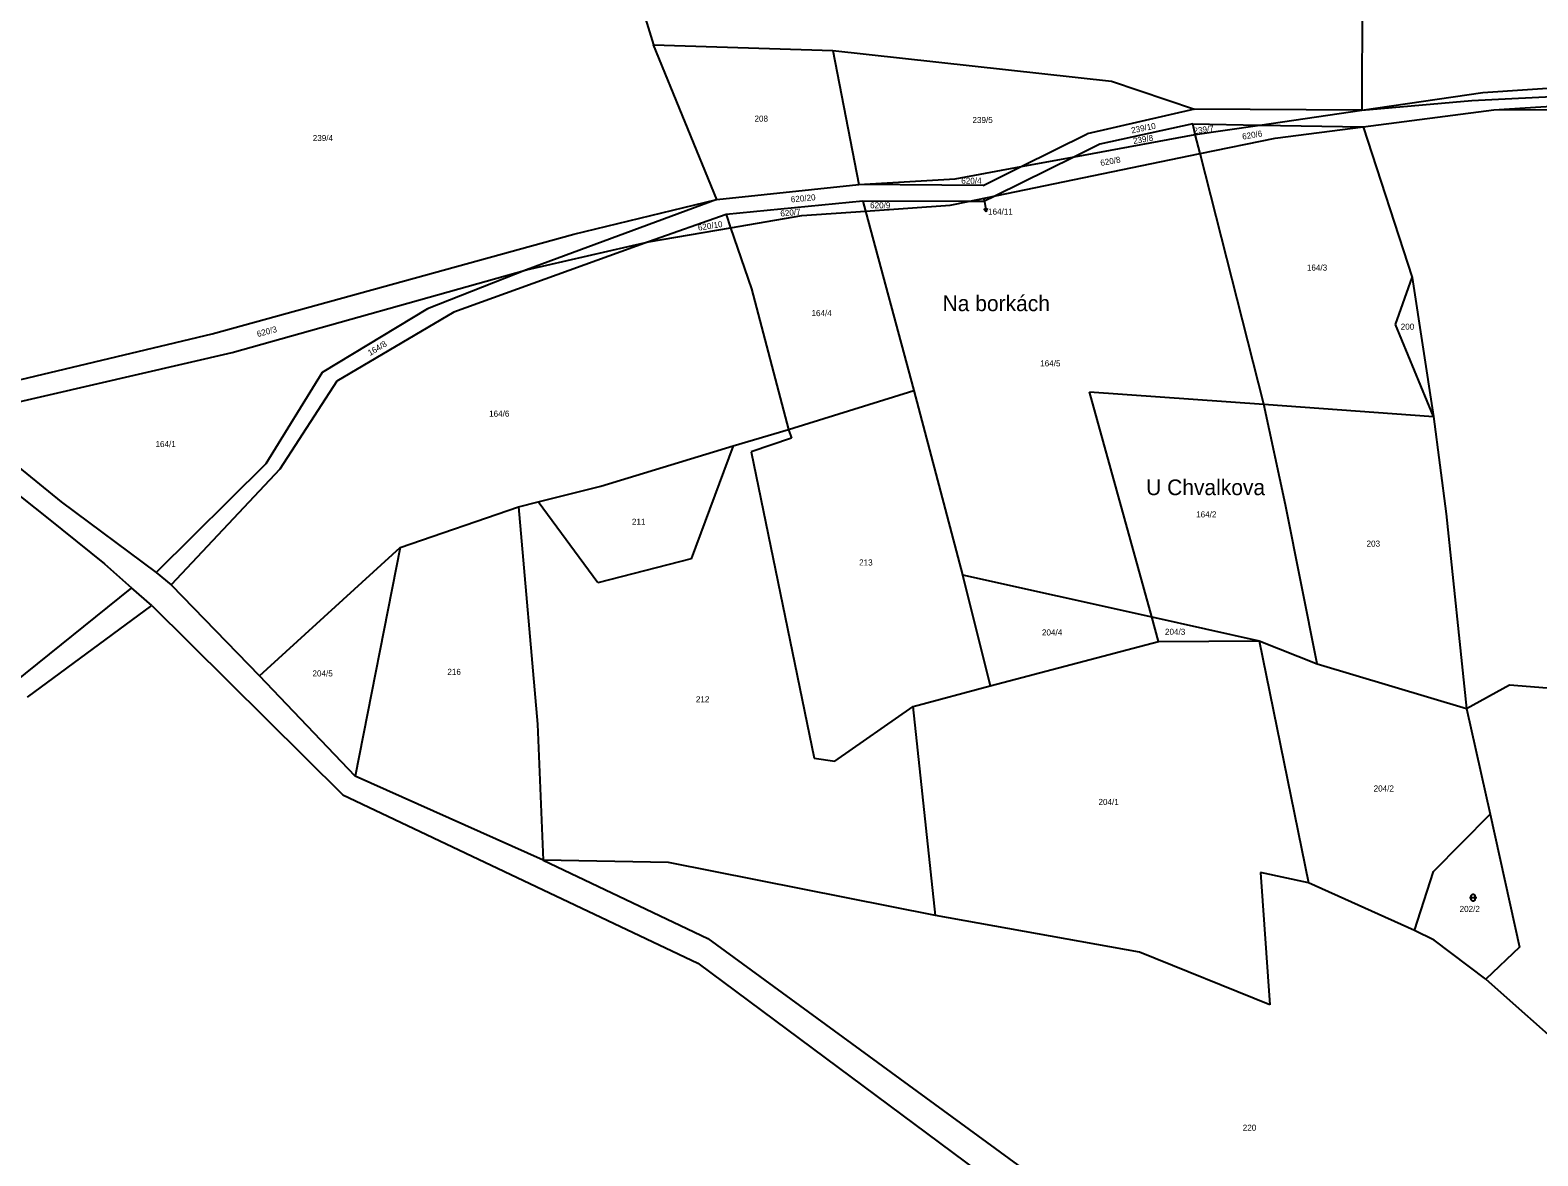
# Model space of a CAD drawing. Extents: x -794421 to -792735, y -1117671 to -1115559.
# Drawn here: x -794007.8 to -793585, y -1116417 to -1116101.2 of the extents above; entities that cross this region are included whole.
import ezdxf

# ---------------------------------------------------------------- set-up
doc = ezdxf.new("R2010")
doc.units = 0
for name, color, linetype in [('Komunikace', 7, 'Continuous'), ('Vrstva 1', 7, 'Continuous'), ('Vrstva 14', 7, 'Continuous'), ('Vrstva 16', 7, 'Continuous'), ('Vrstva 23', 7, 'Continuous'), ('Vrstva 39', 7, 'Continuous')]:
    doc.layers.add(name, color=color, linetype=linetype)

msp = doc.modelspace()

# ---------------------------------------------------------------- linework, layer by layer
at = {"layer": 'Komunikace'}
msp.add_line((-793740.29, -1116148.63), (-793740.17, -1116149.3), dxfattribs=at)
at = {"layer": 'Vrstva 1'}
for p, q in [((-793841.9, -1116076.14), (-793832.93, -1116105.39)), ((-793634.16, -1116081.65), (-793634.36, -1116123.68)), ((-793832.93, -1116105.39), (-793782.69, -1116106.95)), ((-793815.18, -1116148.79), (-793832.93, -1116105.39)), ((-793782.69, -1116106.95), (-793775.4, -1116144.58)), ((-793782.69, -1116106.95), (-793704.56, -1116115.56)), ((-793704.56, -1116115.56), (-793681.22, -1116123.41)), ((-793600.44, -1116118.71), (-793553.62, -1116115.56)), ((-793634.36, -1116123.68), (-793600.44, -1116118.71)), ((-793603.53, -1116120.99), (-793558.72, -1116118.73)), ((-793681.22, -1116123.41), (-793711.33, -1116130.35)), ((-793634.36, -1116123.68), (-793681.22, -1116123.41)), ((-793662.98, -1116127.87), (-793634.36, -1116123.68)), ((-793634.36, -1116123.68), (-793603.53, -1116120.99)), ((-793633.97, -1116128.34), (-793597.29, -1116123.63)), ((-793597.29, -1116123.63), (-793555.45, -1116120.83)), ((-793597.29, -1116123.63), (-793557.09, -1116123.33)), ((-793681.73, -1116127.56), (-793707.83, -1116133.26)), ((-793681.73, -1116127.56), (-793662.98, -1116127.87)), ((-793681.05, -1116130.51), (-793681.73, -1116127.56)), ((-793681.05, -1116130.51), (-793662.98, -1116127.87)), ((-793662.98, -1116127.87), (-793633.97, -1116128.34)), ((-793658.65, -1116131.51), (-793633.97, -1116128.34)), ((-793633.97, -1116128.34), (-793620.23, -1116170.63)), ((-793729.84, -1116139.53), (-793711.33, -1116130.35)), ((-793714.95, -1116136.78), (-793681.05, -1116130.51)), ((-793679.69, -1116135.86), (-793681.05, -1116130.51)), ((-793679.69, -1116135.86), (-793658.65, -1116131.51)), ((-793737.07, -1116147.71), (-793679.69, -1116135.86)), ((-793714.95, -1116136.78), (-793737.07, -1116147.71)), ((-793729.84, -1116139.53), (-793714.95, -1116136.78)), ((-793707.83, -1116133.26), (-793714.95, -1116136.78)), ((-793661.85, -1116206.2), (-793679.69, -1116135.86)), ((-793748.37, -1116142.95), (-793729.84, -1116139.53)), ((-793740.53, -1116144.84), (-793729.84, -1116139.53)), ((-793815.18, -1116148.79), (-793775.4, -1116144.58)), ((-793775.4, -1116144.58), (-793748.37, -1116142.95)), ((-793740.53, -1116144.84), (-793775.4, -1116144.58)), ((-793815.18, -1116148.79), (-793868.58, -1116168.47)), ((-793855.28, -1116158.46), (-793815.18, -1116148.79)), ((-793774.26, -1116149.18), (-793812.61, -1116152.91)), ((-793774.26, -1116149.18), (-793773.5, -1116152)), ((-793744.73, -1116149.29), (-793774.26, -1116149.18)), ((-793749.76, -1116150.33), (-793744.73, -1116149.29)), ((-793744.73, -1116149.29), (-793737.07, -1116147.71)), ((-793740.29, -1116149.3), (-793744.73, -1116149.29)), ((-793737.07, -1116147.71), (-793740.29, -1116149.3)), ((-793812.61, -1116152.91), (-793834.33, -1116160.6)), ((-793812.61, -1116152.91), (-793811.33, -1116156.67)), ((-793811.33, -1116156.67), (-793791.34, -1116153.26)), ((-793791.34, -1116153.26), (-793773.5, -1116152)), ((-793773.5, -1116152), (-793749.76, -1116150.33)), ((-793773.5, -1116152), (-793759.99, -1116202.28)), ((-793956.73, -1116186.47), (-793855.28, -1116158.46)), ((-793834.33, -1116160.6), (-793811.33, -1116156.67)), ((-793811.33, -1116156.67), (-793805.49, -1116173.76)), ((-793834.33, -1116160.6), (-793888.92, -1116180.33)), ((-793868.58, -1116168.47), (-793834.33, -1116160.6)), ((-793951.13, -1116191.65), (-793868.58, -1116168.47)), ((-793868.58, -1116168.47), (-793896.31, -1116179.37)), ((-793624.93, -1116183.83), (-793620.23, -1116170.63)), ((-793620.23, -1116170.63), (-793614.28, -1116209.62)), ((-793805.49, -1116173.76), (-793795.07, -1116213.26)), ((-793896.31, -1116179.37), (-793925.86, -1116197.25)), ((-793888.92, -1116180.33), (-793921.75, -1116199.71)), ((-793614.28, -1116209.62), (-793624.93, -1116183.83)), ((-794016.69, -1116200.78), (-793956.73, -1116186.47)), ((-794016.19, -1116206.71), (-793951.13, -1116191.65)), ((-793925.86, -1116197.25), (-793941.64, -1116222.86)), ((-793921.75, -1116199.71), (-793937.73, -1116224.43)), ((-793795.07, -1116213.26), (-793759.99, -1116202.28)), ((-793759.99, -1116202.28), (-793746.34, -1116254.05)), ((-793710.72, -1116202.69), (-793661.85, -1116206.2)), ((-793693.24, -1116265.77), (-793710.72, -1116202.69)), ((-793655.76, -1116234.44), (-793661.85, -1116206.2)), ((-793661.85, -1116206.2), (-793614.28, -1116209.62)), ((-794035.23, -1116212.34), (-794002.75, -1116238.27)), ((-793810.67, -1116217.86), (-793795.07, -1116213.26)), ((-793795.07, -1116213.26), (-793794.27, -1116215.71)), ((-793614.28, -1116209.62), (-793610.7, -1116236.94)), ((-794020.03, -1116216.53), (-793999.05, -1116233.58)), ((-793794.27, -1116215.71), (-793805.56, -1116219.56)), ((-793847.73, -1116229.19), (-793810.67, -1116217.86)), ((-793810.67, -1116217.86), (-793822.4, -1116249.55)), ((-793805.56, -1116219.56), (-793787.88, -1116305.47)), ((-793941.64, -1116222.86), (-793972.42, -1116253.42)), ((-793937.73, -1116224.43), (-793968.22, -1116256.81)), ((-793865.31, -1116233.55), (-793847.73, -1116229.19)), ((-793999.05, -1116233.58), (-793972.42, -1116253.42)), ((-793870.8, -1116234.91), (-793865.31, -1116233.55)), ((-793848.6, -1116256.32), (-793865.31, -1116233.55)), ((-793646.86, -1116278.95), (-793655.76, -1116234.44)), ((-794002.75, -1116238.27), (-793986.93, -1116250.95)), ((-793903.96, -1116246.38), (-793870.8, -1116234.91)), ((-793870.8, -1116234.91), (-793865.46, -1116295.94)), ((-793610.7, -1116236.94), (-793604.97, -1116291.48)), ((-793943.43, -1116282.4), (-793903.96, -1116246.38)), ((-793903.96, -1116246.38), (-793916.64, -1116310.52)), ((-793986.93, -1116250.95), (-793979.33, -1116257.63)), ((-793822.4, -1116249.55), (-793848.6, -1116256.32)), ((-793972.42, -1116253.42), (-793968.22, -1116256.81)), ((-793746.34, -1116254.05), (-793693.24, -1116265.77)), ((-793746.34, -1116254.05), (-793738.56, -1116285.15)), ((-793979.33, -1116257.63), (-794012.56, -1116284.39)), ((-793973.68, -1116262.66), (-793979.33, -1116257.63)), ((-793968.22, -1116256.81), (-793943.43, -1116282.4)), ((-794008.55, -1116288.34), (-793973.68, -1116262.66)), ((-793973.68, -1116262.66), (-793920.04, -1116315.71)), ((-793693.24, -1116265.77), (-793663.09, -1116272.5)), ((-793691.31, -1116272.74), (-793693.24, -1116265.77)), ((-793738.56, -1116285.15), (-793691.31, -1116272.74)), ((-793691.31, -1116272.74), (-793663.09, -1116272.5)), ((-793663.09, -1116272.5), (-793649.32, -1116340.43)), ((-793663.09, -1116272.5), (-793646.86, -1116278.95)), ((-793646.86, -1116278.95), (-793604.97, -1116291.48)), ((-793916.64, -1116310.52), (-793943.43, -1116282.4)), ((-793760.11, -1116290.96), (-793738.56, -1116285.15)), ((-793604.97, -1116291.48), (-793592.97, -1116284.93)), ((-793592.97, -1116284.93), (-793558.4, -1116287.58)), ((-793782.07, -1116306.26), (-793760.11, -1116290.96)), ((-793753.92, -1116349.61), (-793760.11, -1116290.96)), ((-793604.97, -1116291.48), (-793598.37, -1116321.17)), ((-793865.46, -1116295.94), (-793863.86, -1116334.03)), ((-793787.88, -1116305.47), (-793782.07, -1116306.26)), ((-793863.86, -1116334.03), (-793916.64, -1116310.52)), ((-793920.04, -1116315.71), (-793820.52, -1116362.92)), ((-793614.27, -1116337.29), (-793598.37, -1116321.17)), ((-793598.37, -1116321.17), (-793590.13, -1116358.46)), ((-793828.77, -1116334.72), (-793863.86, -1116334.03)), ((-793863.86, -1116334.03), (-793817.71, -1116356.03)), ((-793753.92, -1116349.61), (-793828.77, -1116334.72)), ((-793649.32, -1116340.43), (-793662.76, -1116337.54)), ((-793662.76, -1116337.54), (-793660.1, -1116374.64)), ((-793619.6, -1116353.8), (-793614.27, -1116337.29)), ((-793619.6, -1116353.8), (-793649.32, -1116340.43)), ((-793696.72, -1116359.85), (-793753.92, -1116349.61)), ((-793817.71, -1116356.03), (-793707.67, -1116436.43)), ((-793614.07, -1116356.51), (-793619.6, -1116353.8)), ((-793599.56, -1116367.45), (-793614.07, -1116356.51)), ((-793660.1, -1116374.64), (-793696.72, -1116359.85)), ((-793590.13, -1116358.46), (-793599.56, -1116367.45)), ((-793820.52, -1116362.92), (-793715.41, -1116441.11)), ((-793599.56, -1116367.45), (-793573.29, -1116390.8))]:
    msp.add_line(p, q, dxfattribs=at)
at = {"layer": 'Vrstva 16'}
for p, q in [((-793740.17, -1116149.3), (-793739.631, -1116152.251)), ((-793739.631, -1116152.251), (-793740.303, -1116151.357)), ((-793739.631, -1116152.251), (-793739.319, -1116151.177))]:
    msp.add_line(p, q, dxfattribs=at)
at = {"layer": 'Vrstva 23'}
for p, q in [((-793604.13, -1116344.56), (-793602.13, -1116344.56)), ((-793603.63, -1116343.96), (-793603.53, -1116343.76)), ((-793603.63, -1116345.16), (-793603.63, -1116343.96)), ((-793603.53, -1116343.76), (-793603.43, -1116343.66)), ((-793603.43, -1116343.66), (-793603.23, -1116343.56)), ((-793603.23, -1116343.56), (-793603.03, -1116343.56)), ((-793603.03, -1116343.56), (-793602.83, -1116343.66)), ((-793602.83, -1116343.66), (-793602.73, -1116343.76)), ((-793602.73, -1116343.76), (-793602.63, -1116343.96)), ((-793602.63, -1116343.96), (-793602.63, -1116345.16)), ((-793603.53, -1116345.36), (-793603.63, -1116345.16)), ((-793603.43, -1116345.46), (-793603.53, -1116345.36)), ((-793603.23, -1116345.56), (-793603.43, -1116345.46)), ((-793603.03, -1116345.56), (-793603.23, -1116345.56)), ((-793602.83, -1116345.46), (-793603.03, -1116345.56)), ((-793602.73, -1116345.36), (-793602.83, -1116345.46)), ((-793602.63, -1116345.16), (-793602.73, -1116345.36))]:
    msp.add_line(p, q, dxfattribs=at)

# ---------------------------------------------------------------- texts
at = {"layer": 'Vrstva 14'}
for s, height, p in [('208', 1.7, (-793804.646, -1116126.91)), ('239/5', 1.7, (-793743.526, -1116127.3)), ('239/4', 1.7, (-793928.516, -1116132.35)), ('620/4', 1.7, (-793746.665, -1116144.35)), ('620/9', 1.7, (-793772.229, -1116151.22)), ('164/11', 0.1, (-793740.497, -1116148.63)), ('164/3', 1.7, (-793649.739, -1116168.7)), ('164/4', 1.7, (-793788.665, -1116181.47)), ('200', 1.7, (-793623.425, -1116185.26)), ('164/5', 1.7, (-793724.525, -1116195.55)), ('164/6', 1.7, (-793879.059, -1116209.66)), ('164/1', 1.7, (-793972.622, -1116218.2)), ('211', 1.7, (-793839.013, -1116239.98)), ('164/2', 1.7, (-793680.799, -1116237.93)), ('203', 1.7, (-793633.006, -1116246.12)), ('213', 1.7, (-793775.3, -1116251.41)), ('204/4', 1.7, (-793724.041, -1116271.04)), ('204/3', 1.7, (-793689.535, -1116270.86)), ('204/5', 1.7, (-793928.591, -1116282.53)), ('216', 1.7, (-793890.77, -1116282.09)), ('212', 1.7, (-793821.08, -1116289.78)), ('204/2', 1.7, (-793631.025, -1116314.81)), ('204/1', 1.7, (-793708.178, -1116318.58)), ('202/2', 1.7, (-793606.919, -1116348.59)), ('220', 1.7, (-793667.726, -1116409.95))]:
    msp.add_text(s, height=height, dxfattribs=at).set_placement(p)
for s, rotation, p in [('239/10', 11.20077, (-793698.816, -1116130.219)), ('239/7', 7.12296, (-793681.419, -1116130.349)), ('239/8', 9.73251, (-793698.329, -1116133.19)), ('620/6', 9.65097, (-793667.74, -1116131.966)), ('620/8', 9.89307, (-793707.497, -1116139.337)), ('620/20', 5.2299, (-793794.38, -1116149.585)), ('620/7', 5.5377, (-793797.309, -1116153.551)), ('620/10', 9.07677, (-793820.371, -1116157.521)), ('620/3', 14.88375, (-793943.932, -1116187.338)), ('164/8', 30.88107, (-793912.44, -1116192.652))]:
    msp.add_text(s, height=1.7, rotation=rotation, dxfattribs=at).set_placement(p)
at = {"layer": 'Vrstva 16'}
msp.add_text('164/11', height=1.7, dxfattribs=at).set_placement((-793739.15, -1116152.99))
at = {"layer": 'Vrstva 39'}
for s, p in [('Na borkách', (-793751.89, -1116180.07)), ('U Chvalkova', (-793694.81, -1116231.68))]:
    msp.add_text(s, height=4.4, dxfattribs=at).set_placement(p)

doc.saveas('drawing.dxf')
